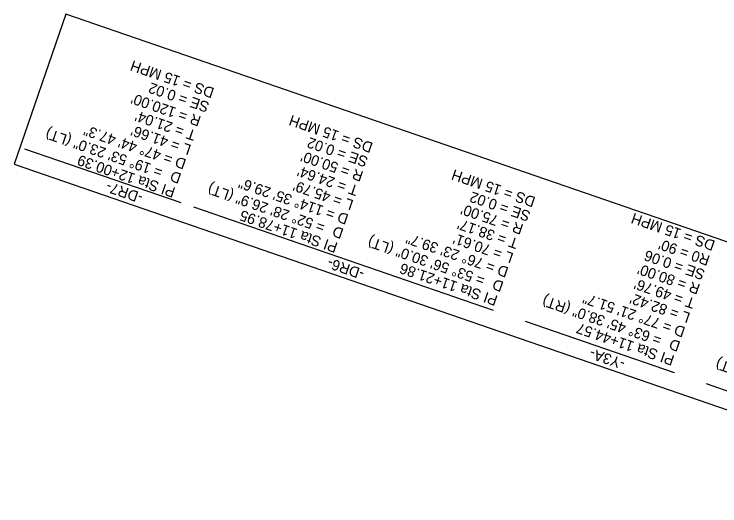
# Model space of a CAD drawing. Extents: x 472216 to 481979, y 489069 to 507339.
# Drawn here: x 479990.7 to 480456.8, y 492695.7 to 493020.3 of the extents above; entities that cross this region are included whole.
import ezdxf

# ---------------------------------------------------------------- set-up
doc = ezdxf.new("R2010")
doc.units = 0
doc.layers.add('Exist Horizontal Alignment Point', color=7, linetype='Continuous')
doc.layers.add('Prop Rem of Exist Asph Pvmt', color=7, linetype='Continuous')

msp = doc.modelspace()

# ---------------------------------------------------------------- linework, layer by layer
at = {"layer": 'Exist Horizontal Alignment Point'}
msp.add_lwpolyline([(480679.77, 492794.65), (480615.15, 492816.92), (480566.07, 492833.82), (480024.85, 493020.3), (479990.74, 492921.32), (480645.67, 492695.67)], close=True, dxfattribs=at)
at = {"layer": 'Prop Rem of Exist Asph Pvmt'}
for p, q in [((480101.13, 492895.64), (479997.82, 492931.24)), ((480307.29, 492824.61), (480109.51, 492892.76)), ((480426.78, 492783.45), (480328.53, 492817.29)), ((480639.22, 492710.25), (480448.02, 492776.13))]:
    msp.add_line(p, q, dxfattribs=at)

# ---------------------------------------------------------------- texts
for s, p in [('DS = 15 MPH', (480123.45, 492971.23)), ('SE = 0.02', (480120.19, 492961.78)), ("R = 120.00'", (480114.74, 492952.61)), ("T = 21.04'", (480111.48, 492943.15)), ('DS = 15 MPH', (480228.22, 492935.13)), ('= 19%%d 53\' 23.0" (LT)', (480089.46, 492918.7)), ('D = 47%%d 44\' 47.3"', (480104.96, 492924.24)), ("L = 41.66'", (480108.22, 492933.7)), ('SE = 0.02', (480224.96, 492925.68)), ('PI Sta 12+00.39', (480097.81, 492905.56)), ("R = 50.00'", (480221.89, 492916.17)), ("T = 24.64'", (480218.64, 492906.71)), ('DS = 15 MPH', (480335.53, 492899.24)), ('D', (480101.71, 492914.79)), ('-DR7-', (480076.41, 492901.84)), ('= 52%%d 28\' 26.9" (LT)', (480196.62, 492882.26)), ('D = 114%%d 35\' 29.6"', (480212.12, 492887.8)), ("L = 45.79'", (480215.38, 492897.26)), ('SE = 0.02', (480332.28, 492889.78)), ("R = 75.00'", (480327.56, 492881.2)), ('PI Sta 11+78.95', (480204.97, 492869.11)), ('DS = 15 MPH', (480454.17, 492870.48)), ("T = 38.17'", (480324.3, 492871.74)), ('D', (480208.86, 492878.35)), ('= 53%%d 56\' 30.0" (LT)', (480302.28, 492847.29)), ('D = 76%%d 23\' 39.7"', (480317.78, 492852.84)), ("L = 70.61'", (480321.04, 492862.29)), ("R0 = 90'", (480450.77, 492860.62)), ('SE = 0.06', (480447.52, 492851.17)), ('-DR6-', (480222.58, 492851.48)), ('PI Sta 11+21.86', (480310.63, 492834.15)), ("R = 80.00'", (480444.26, 492841.71)), ('D', (480314.53, 492843.38)), ("T = 49.76'", (480441, 492832.26)), ('= 63%%d 45\' 38.0" (RT)', (480418.98, 492807.8)), ('D = 77%%d 21\' 51.7"', (480434.49, 492813.35)), ("L = 82.42'", (480437.74, 492822.81)), ('PI Sta 11+44.57', (480427.33, 492794.66)), ('D', (480431.23, 492803.9)), ('-Y3A-', (480394.77, 492792.15)), ('= 1%%d 27\' 31.2" (RT)', (480528.52, 492767.89))]:
    msp.add_text(s, height=7, rotation=160.9892, dxfattribs=at).set_placement(p)

doc.saveas('drawing.dxf')
